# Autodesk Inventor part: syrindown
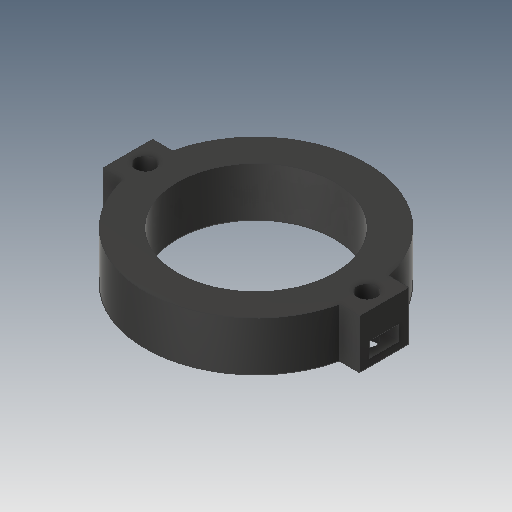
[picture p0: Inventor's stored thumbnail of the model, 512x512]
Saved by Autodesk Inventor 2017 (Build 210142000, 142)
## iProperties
Created: 2018-10
Part Number: syrindown
Material: Plastic, Opaque Black
Document SubType Name: Modeling
Designer: JK
Density: 0.952 g/cm^3
Appearance: Smooth - Black
Author: JK
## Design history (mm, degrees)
sketch "Sketch1"
  geometry: C1 r 16 at (0, 0); C2 r 22.5 at (0, 0); 1 further point
  constraints: 2 centre point, 2 coincident
  dimensions: "d0" = 32 diameter of C1; "d1" = 45 diameter of C2
extrude "Extrusion1" new body sketch "Sketch1" distance "d2" = 10; taper "d3" = 0 deg
sketch "Sketch2"
  geometry: L1 (-26, -5)-(-16, -5); L2 (-16, -5)-(-16, 5); L3 (-16, 5)-(-26, 5); L4 (-26, 5)-(-26, -5); L5 (16, -5)-(26, -5); L6 (26, -5)-(26, 5); L7 (26, 5)-(16, 5); L8 (16, 5)-(16, -5); C1 r 16 at (0, 0) reference; 1 further point
  constraints: 16 end point, 4 parallel, 3 collinear, 2 horizontal, 2 perpendicular, 2 tangent
  dimensions: "d4" = 5 distance from line of point (0, 0) L1; "d5" = 10 distance of L3.end L1.start; "d6" = 10 distance of L2.end L3.end
extrude "Extrusion2" join sketch "Sketch2" distance "d7" = 10; taper "d8" = 0 deg
sketch "Sketch3"
  geometry: L1 (2, -5.5)-(8, -5.5); L2 (8, -5.5)-(8, -8.5); L3 (8, -8.5)-(2, -8.5); L4 (2, -8.5)-(2, -5.5); L5 (2, -5.5)-(8, -8.5); L6 (8, -5.5)-(2, -8.5); L7 (10, -10)-(0, -10) reference; 4 further points
  constraints: 12 end point, 4 midpoint, 2 parallel, 1 horizontal, 1 perpendicular, 1 vertical alignment
  dimensions: "d9" = 6 distance of L1.start L1.end; "d10" = 3 distance of L1.end L2.end; "d11" = 3 distance of point (5, -10) point (5, -7)
extrude "Extrusion3" cut sketch "Sketch3" distance "d12" = 7; taper "d13" = 0 deg
sketch "Sketch4"
  geometry: L1 (8, -8.5)-(8, -5.5) reference; L2 (2, -5.836)-(8, -5.836); L3 (8, -5.836)-(8, -8.164); L4 (8, -8.164)-(2, -8.164); L5 (2, -8.164)-(2, -5.836); L6 (2, -5.836)-(8, -8.164); L7 (8, -5.836)-(2, -8.164); 2 further points
  constraints: 12 end point, 2 midpoint, 2 parallel, 1 horizontal, 1 perpendicular, 1 point on line
  dimensions: "d14" = 6 distance of L2.start L2.end; "d16" = 3 distance of point (5, -10) point (5, -7)
extrude "Extrusion4" cut sketch "Sketch4" distance "d17" = 7; taper "d18" = 0 deg
sketch "Sketch5"
  geometry: L1 (-26, 3)-(-26, -3) reference; L2 (26, 5)-(26, -5) reference; C1 r 2 at (-22.5, 0); C2 r 2 at (22.5, 0); 1 further point
  constraints: 2 centre point
  dimensions: "d19" = 4 diameter of C1; "d20" = 3.5 distance from line of L1 C1.centre; "d21" = 3.5 distance from line of L2 C2.centre; "d22" = 4 diameter of C2
extrude "Extrusion5" cut sketch "Sketch5" distance "d23" = 41; taper "d24" = 0 deg
body "Solid1"
